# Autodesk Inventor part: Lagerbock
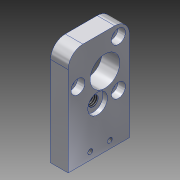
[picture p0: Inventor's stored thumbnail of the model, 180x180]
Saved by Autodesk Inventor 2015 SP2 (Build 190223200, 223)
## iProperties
Created: 2013-12
Part Number: Lagerbock
Material: Aluminium 6061
Document SubType Name: Modeling
Designer: rYan
Mass: 17.8038 g
Surface Area: 41.0197 cm^2
Volume: 6.56968 cm^3
Density: 2.71 g/cm^3
Appearance: Aluminium - flach
Author: rYan
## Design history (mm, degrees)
sketch "Skizze1"
  geometry: L1 (-20, 0)-(15, 0) reference; L2 (0, 51)-(0, -8.5) reference; L3 (-15, 0)-(10, 0); L4 (-15, 0)-(-15, 42.5); L5 (-15, 42.5)-(10, 42.5); L6 (10, 42.5)-(10, 0); 1 further point
  constraints: 8 end point, 1 horizontal, 1 parallel, 1 point on line
  dimensions: "d4" = 42.5 distance between parallel lines of L1 L5; "d61" = 15 distance between parallel lines of L4 L2; "d62" = 10 distance between parallel lines of L6 L2
extrude "Extrusion1" new body sketch "Skizze1" stored distance "d5" = 7.2; taper "d6" = 0 deg
sketch "Skizze2"
  geometry: L1 (-51, 0)-(8.5, 0) reference; L2 (0, -20)-(0, 15) reference; 2 further points
  constraints: 1 point on line
  dimensions: "d7" = 28.5 distance from line of point (-28.5, 0) L2
hole "Motorwelle" sketch "Skizze2" at (-28.5, 0) diameter "d8" = 12.1; stored, may be unused: countersink angle "d12" = 90 deg, drill point angle "d14" = 118 deg; dims "d9" = 6, "d10" = 12.1, "d11" = 3.3, "d13" = 8
sketch "Skizze3"
  geometry: L1 (-51, 0)-(8.5, 0) reference; L2 (-28.5, 0)-(-18.542, -3); C1 r 6.05 at (-28.5, 0) reference; 1 further point
  constraints: 2 end point, 1 coincident
  dimensions: "d15" = 10.4 distance of L2.start L2.end; "d60" = 3 distance from line of L1 L2.end
hole "Radwelle" sketch "Skizze3" at (-18.542, -3) diameter "d17" = 4.134; stored, may be unused: countersink angle "d21" = 90 deg, drill point angle "d23" = 118 deg; dims "d18" = 6, "d19" = 8, "d20" = 1.8, "d22" = 8
sketch "Skizze4" dims "d24" = 22
  geometry: L1 (-28.5, 0)-(-18.974, 5.5); L2 (0, -20.2)-(0, 16.2) reference; C1 r 6.05 at (-28.5, 0) reference; 1 further point
  constraints: 2 end point, 1 coincident, 3 other
  dimensions: "d25" = 300 deg dimension on L2 L1
hole "Motorschrauben" sketch "Skizze4" at (-18.974, 5.5) diameter "d27" = 3.2; stored, may be unused: countersink angle "d31" = 90 deg, drill point angle "d33" = 118 deg; dims "d28" = 6, "d29" = 5.7, "d30" = 3, "d32" = 8
pattern_circular "Runde Anordnung1" dims angle "d35" = 360 deg
sketch "Skizze5"
  geometry: L1 (0, -20)-(0, 15) reference; L2 (-51, 0)-(8.5, 0) reference; L3 (-3, -6)-(-3, 2); 1 further point
  constraints: 2 end point, 1 vertical
  dimensions: "d37" = 8 distance of L3.end L3.start; "d39" = 3 distance from line of L1 L3.start; "d63" = 6 distance from line of L3.start L2
hole "Encoderbolzen" sketch "Skizze5" at (-3, -6), (-3, 2) diameter "d40" = 2.013; stored, may be unused: countersink angle "d44" = 90 deg, drill point angle "d46" = 118 deg; dims "d41" = 6, "d42" = 5.7, "d43" = 3.5, "d45" = 8
sketch "Skizze6"
  geometry: L1 (7.2, 0)-(0, 0) reference; L2 (0, -25)-(0, 0) reference; L3 (0, -25)-(7.2, -25) reference; L4 (7.2, 0)-(7.2, -25) reference; L5 (3.6, -25)-(3.6, 0); 4 further points
  constraints: 3 point on line, 2 end point, 2 midpoint
  dimensions: "d47" = 8 distance of point (3.6, -13) point (3.6, -21); "d49" = 8 distance of point (3.6, -5) point (3.6, -13) (= d47); "d50" = 3 distance of point (3.6, -13) point (3.6, -10)
hole "Montagebohrungen" sketch "Skizze6" at (3.6, -21), (3.6, -13), (3.6, -5) diameter "d51" = 2.459; stored, may be unused: countersink angle "d55" = 82 deg, drill point angle "d57" = 118 deg; dims "d52" = 6, "d53" = 3.023, "d54" = 3.5, "d56" = 8
fillet "Rundung2" dims "d59" = 6
mirror "Spiegeln1"
node "Volumenkörper1"
node "Projizierte Kontur1"
